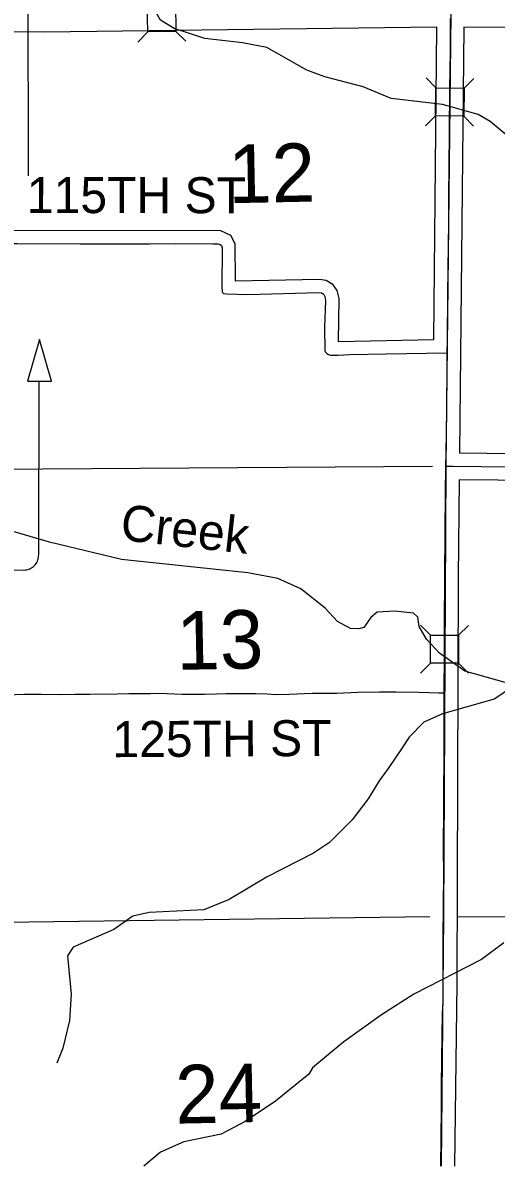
# Model space of a CAD drawing. Extents: x 10133 to 81668, y 7924 to 11018.
# Drawn here: x 12064.5 to 12222.4, y 8510.5 to 8891.7 of the extents above; entities that cross this region are included whole.
import ezdxf

# ---------------------------------------------------------------- set-up
doc = ezdxf.new("R2010")
doc.units = 0
for name, color, linetype in [('tdCoCityStreetMajor', 7, 'Continuous'), ('tdCoCityStreetMinor', 7, 'Continuous'), ('tdCoCorpTxt', 7, 'Continuous'), ('tdCoDirctArrow', 7, 'Continuous'), ('tdCoHydroRiver', 7, 'Continuous'), ('tdCoPriNonDiv', 7, 'Continuous'), ('tdCoRROwnerTxt', 7, 'Continuous'), ('tdCoShieldCoRte', 7, 'Continuous'), ('tdCoShieldStRte', 7, 'Continuous'), ('tdCoStrucNonDivPri', 7, 'Continuous'), ('tdCoTwpNameTxt', 7, 'Continuous')]:
    doc.layers.add(name, color=color, linetype=linetype)

msp = doc.modelspace()

# ---------------------------------------------------------------- linework, layer by layer
at = {"layer": 'tdCoCityStreetMajor'}
msp.add_lwpolyline([(12130.87, 8805.87), (12130.84, 8803.9), (12130.95, 8802.01), (12131.06, 8801.72), (12131.47, 8801.42), (12132.5, 8801.27), (12139.57, 8801.12), (12163.28, 8801.72), (12164.17, 8801.61), (12164.65, 8801.35), (12164.87, 8801.05), (12165.24, 8800.42), (12165.43, 8799.13), (12165.13, 8790.25), (12165.2, 8782.33), (12165.43, 8781.93), (12165.91, 8781.48), (12166.43, 8781.11), (12167.13, 8780.89), (12169.61, 8780.89), (12173.6, 8781.15), (12185.66, 8781.33), (12206.09, 8781.71)], dxfattribs=at)
at = {"layer": 'tdCoCityStreetMinor'}
for points in [[(12205.62, 8743.86), (12205.69, 8748.27), (12205.91, 8761.85), (12206.06, 8777.98), (12206.09, 8781.71), (12206.13, 8785.93), (12206.31, 8801.1), (12206.35, 8809.57), (12206.57, 8825.18), (12206.57, 8833.76), (12206.72, 8843.86), (12206.83, 8854.92), (12206.98, 8869.82), (12207.13, 8882.11), (12207.13, 8893.09)], [(11979.87, 8793.33), (11979.86, 8794.38), (11979.9, 8804.37), (11980.08, 8815.25), (11980.11, 8818.02), (11982.99, 8817.99), (12013.06, 8818.14), (12042.36, 8818.14), (12053.9, 8818.14), (12056.26, 8818.14), (12062.74, 8818.14), (12083.75, 8817.96), (12106.76, 8818.03), (12115.56, 8818.07), (12127.92, 8818.03), (12129.66, 8818.03), (12130.29, 8817.81), (12130.73, 8817.47), (12130.99, 8816.7), (12130.99, 8814.15), (12130.87, 8805.87)], [(12205.04, 8668.35), (12205.04, 8669.7), (12205.19, 8680.13), (12205.2, 8691.05), (12205.24, 8706.95), (12205.43, 8722.08), (12205.5, 8734.81), (12205.62, 8743.86)], [(12205.62, 8743.86), (12208.06, 8743.84), (12236.4, 8743.51), (12267.29, 8743.14), (12283.01, 8742.91), (12304.46, 8742.84), (12317.32, 8742.93)], [(12055.69, 8667.51), (12065.05, 8667.85), (12070.64, 8667.88), (12076.89, 8667.77), (12081.99, 8667.92), (12086.88, 8667.88), (12095.83, 8667.96), (12099.86, 8668.11), (12104.19, 8668.11), (12107.04, 8668.14), (12109.74, 8668.22), (12112.7, 8668.07), (12117.62, 8667.92), (12125.12, 8667.92), (12129.12, 8668.03), (12132.38, 8668.14), (12142.21, 8668.14), (12145.88, 8668.03), (12148.98, 8667.81), (12153.28, 8667.92), (12161.15, 8668.22), (12169.14, 8668.25), (12176.25, 8668.55), (12183.53, 8668.62), (12189.01, 8668.66), (12196.59, 8668.59), (12203.25, 8668.33), (12205.04, 8668.35)], [(12203.93, 8510.55), (12204.19, 8529.61), (12204.15, 8537.68), (12204.3, 8545.89), (12204.34, 8554.14), (12204.52, 8561.43), (12204.67, 8565.46), (12204.74, 8571.6), (12204.71, 8577.41), (12204.71, 8580.59), (12204.71, 8585.4), (12204.74, 8590.13), (12204.79, 8593.78), (12204.85, 8598.97), (12204.93, 8606.33), (12204.85, 8617.99), (12204.96, 8628.53), (12204.96, 8637.04), (12205, 8644.73), (12205.04, 8658.05), (12205.04, 8668.35)]]:
    msp.add_lwpolyline(points, dxfattribs=at)
at = {"layer": 'tdCoDirctArrow'}
for points in [[(12066.36, 8840.71), (12066.29, 8903.61), (12066.33, 8904.15), (12066.38, 8904.48), (12066.47, 8904.91), (12066.61, 8905.33), (12066.78, 8905.73), (12066.99, 8906.12), (12067.23, 8906.48), (12067.5, 8906.83), (12067.8, 8907.14), (12068.13, 8907.44), (12068.48, 8907.7), (12068.86, 8907.92), (12069.25, 8908.12), (12069.66, 8908.28), (12070.08, 8908.4), (12070.51, 8908.48), (12070.94, 8908.53), (12071.38, 8908.54), (12129.25, 8908.69)], [(12001.95, 8709.33), (12064.86, 8709.26), (12065.4, 8709.29), (12065.73, 8709.34), (12066.15, 8709.44), (12066.57, 8709.58), (12066.97, 8709.75), (12067.36, 8709.96), (12067.73, 8710.2), (12068.07, 8710.47), (12068.39, 8710.77), (12068.68, 8711.1), (12068.94, 8711.45), (12069.17, 8711.82), (12069.36, 8712.22), (12069.52, 8712.62), (12069.64, 8713.04), (12069.73, 8713.47), (12069.77, 8713.91), (12069.78, 8714.35), (12069.93, 8772.22)]]:
    msp.add_lwpolyline(points, dxfattribs=at)
msp.add_lwpolyline([(12074.1, 8772.18), (12070.01, 8786.05), (12066.02, 8772.26)], close=True, dxfattribs=at)
at = {"layer": 'tdCoHydroRiver'}
for points in [[(12228.37, 8852.05), (12220.43, 8858.77), (12216.37, 8861.06), (12204.46, 8864.4), (12187.38, 8866.45), (12178.07, 8870.31), (12165.23, 8873.63), (12159.27, 8875.89), (12145.87, 8883.45), (12137.79, 8884.97), (12125.21, 8886.39), (12114.97, 8889.76), (12110.42, 8892.52), (12106.01, 8900.49), (12103.84, 8902.58), (12095.98, 8905.28), (12081.04, 8906.66), (12065.87, 8907.1), (12057.78, 8909.32)], [(12227.18, 8670.64), (12226.21, 8671.57), (12211.93, 8675.57), (12203.54, 8681.57), (12199.19, 8686.23), (12196.74, 8690.45), (12196.22, 8693.52), (12194.77, 8694.91), (12188.6, 8695.51), (12182.69, 8695.16), (12180.59, 8693.47), (12178.28, 8690.11), (12176.63, 8689.61), (12173.79, 8689.79), (12169.48, 8692.08), (12165.38, 8696.5), (12157.21, 8702.98), (12149.57, 8706.4), (12139.59, 8708.35), (12097.36, 8712.78), (12073.34, 8718.5), (12042.15, 8727.64), (12018.42, 8730.29)], [(12227.18, 8670.64), (12226.95, 8669.68), (12221.77, 8666.24), (12204.47, 8661.34), (12198.32, 8658.59), (12193.4, 8653.49)], [(12193.4, 8653.49), (12190.84, 8649.63), (12186.42, 8643.13), (12183.39, 8639.02), (12179.68, 8633), (12174.31, 8626), (12166.82, 8618.48), (12161.44, 8614.83), (12145.95, 8606.97), (12133.31, 8599.4), (12124.84, 8595.93), (12106.63, 8595.12), (12101.2, 8593.84), (12094.89, 8589.46), (12081.26, 8583.53), (12079.42, 8580.65), (12080.6, 8567.89), (12080.05, 8559.12), (12077.85, 8549.84), (12075.81, 8544.83)], [(12224.97, 8584.97), (12217.49, 8579.38), (12194.97, 8567.84), (12184.2, 8561.02), (12171.58, 8552.02), (12167.85, 8548.88), (12161.08, 8543.31), (12159.94, 8541.16), (12148.74, 8532.19), (12138.68, 8525.38), (12130.7, 8521.2), (12118.2, 8518.61), (12110.45, 8515.15), (12104.9, 8510.55)]]:
    msp.add_lwpolyline(points, dxfattribs=at)
at = {"layer": 'tdCoPriNonDiv'}
for points in [[(12169.68, 8785.4), (12201.63, 8786.13), (12202.63, 8890.2), (12071.72, 8888.56), (11985.35, 8888.99), (11984.65, 8822.5), (12130.42, 8822.46), (12133.73, 8820.83), (12135.26, 8818.12), (12135.37, 8805.71), (12163.5, 8806.21), (12165.69, 8805.84), (12167.73, 8804.63), (12169.29, 8802.39), (12169.88, 8799.76), (12169.68, 8785.4)], [(12312.97, 8747.4), (12312.27, 8889.58), (12211.63, 8890.25), (12210.19, 8748.31), (12283.05, 8747.41), (12312.97, 8747.4)], [(12408.9, 8654.63), (12394.55, 8654.46), (12392.01, 8655.36), (12389.99, 8657.23), (12389.21, 8659.4), (12389.2, 8662.73), (12323.94, 8663.33), (12321.06, 8663.8), (12318.42, 8665.02), (12314.69, 8669.09), (12313.7, 8673.74), (12312.91, 8738.4), (12210.06, 8739.32), (12209.74, 8706.92), (12209.24, 8571.54), (12208.52, 8510.55)]]:
    msp.add_lwpolyline(points, dxfattribs=at)
at = {"layer": 'tdCoShieldCoRte'}
for points in [[(12118.67, 8901.51), (12115.4, 8898.15), (12115.54, 8888.76)], [(12102.89, 8885.26), (12106.16, 8888.62), (12106.02, 8898.01)], [(12118.83, 8885.57), (12115.54, 8888.76), (12106.16, 8888.62)], [(12199.01, 8873.38), (12202.29, 8870.03), (12211.67, 8869.93)], [(12214.95, 8873.15), (12211.67, 8869.93), (12211.58, 8860.55)], [(12198.85, 8857.36), (12202.2, 8860.64), (12202.29, 8870.03)], [(12214.86, 8857.2), (12211.58, 8860.55), (12202.2, 8860.64)], [(12197.19, 8690.91), (12200.51, 8687.59), (12209.89, 8687.57)], [(12213.14, 8690.82), (12209.89, 8687.57), (12209.88, 8678.19)], [(12197.17, 8674.89), (12200.49, 8678.21), (12200.51, 8687.59)], [(12213.19, 8674.87), (12209.88, 8678.19), (12200.49, 8678.21)]]:
    msp.add_lwpolyline(points, dxfattribs=at)
at = {"layer": 'tdCoStrucNonDivPri'}
for points in [[(12054.84, 8742.93), (12201.17, 8743.83)], [(12058.12, 8591.84), (12200.31, 8593.72)], [(12209.32, 8593.77), (12356.61, 8593.31)]]:
    msp.add_lwpolyline(points, dxfattribs=at)
at = {"layer": 'tdCoTwpNameTxt'}
msp.add_lwpolyline([(12206.7, 9053.29), (12207.28, 8894.75), (12205.62, 8743.86), (12204.79, 8593.78), (12204.03, 8510.55)], dxfattribs=at)

# ---------------------------------------------------------------- texts
at = {"layer": 'tdCoCorpTxt'}
msp.add_text('Creek', height=12, rotation=353.7138, dxfattribs=at).set_placement((12096.71, 8719.31))
at = {"layer": 'tdCoRROwnerTxt'}
for s, rotation, p in [('12', 1.147, (12133.15, 8831.52)), ('13', 1.1469, (12115.89, 8675.95)), ('24', 1.147, (12115.5, 8524.7))]:
    msp.add_text(s, height=19.5, rotation=rotation, dxfattribs=at).set_placement(p)
at = {"layer": 'tdCoShieldStRte'}
for s, rotation, p in [('115TH ST', 359.9544, (12065.82, 8828.25)), ('125TH ST', 0.3237, (12094.39, 8646.86))]:
    msp.add_text(s, height=12, rotation=rotation, dxfattribs=at).set_placement(p)

doc.saveas('drawing.dxf')
